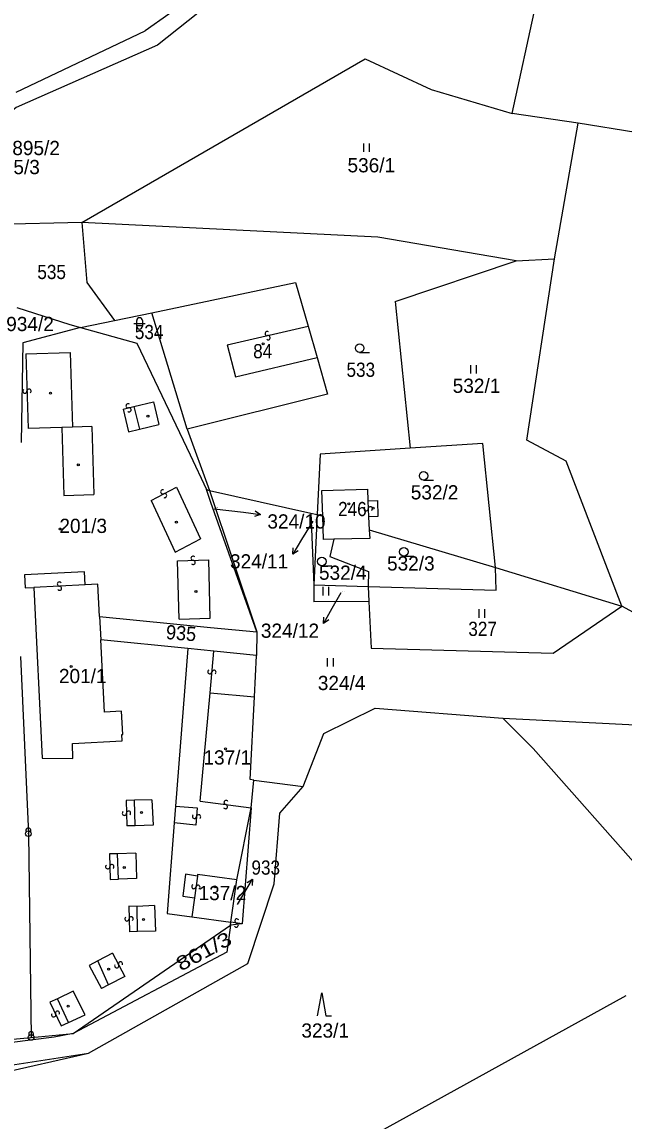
# Model space of a CAD drawing. Extents: x -680102 to -677253, y -1007548 to -1006096.
# Drawn here: x -679408.3 to -679302.6, y -1007390.7 to -1007197.5 of the extents above; entities that cross this region are included whole.
import ezdxf
from ezdxf.enums import TextEntityAlignment as Align

# ---------------------------------------------------------------- set-up
doc = ezdxf.new("R2010")
doc.units = 0
for name, color, linetype, lineweight in [('1', 7, 'Continuous', 25), ('16', 7, 'Continuous', 25), ('24', 7, 'Continuous', 25), ('25', 7, 'Continuous', 25), ('4', 7, 'Continuous', 25)]:
    doc.layers.add(name, color=color, linetype=linetype, lineweight=lineweight)
doc.layers.add('18', color=7, linetype='Continuous')
doc.layers.add('19', color=7, linetype='Continuous')

msp = doc.modelspace()

# ---------------------------------------------------------------- linework, layer by layer
at = {"layer": '1'}
for p, q in [((-679373.36, -1007189.63), (-679386.69, -1007199.1)), ((-679409.36, -1007209.85), (-679386.69, -1007199.1)), ((-679397.84, -1007232.76), (-679414.73, -1007233.19)), ((-679345.8, -1007235.33), (-679397.84, -1007232.76)), ((-679397.84, -1007232.76), (-679396.93, -1007243.35)), ((-679321.52, -1007239.5), (-679345.8, -1007235.33)), ((-679342.81, -1007246.67), (-679321.52, -1007239.5)), ((-679321.52, -1007239.5), (-679314.77, -1007239.17)), ((-679396.93, -1007243.35), (-679392.07, -1007249.98)), ((-679342.81, -1007246.67), (-679340.14, -1007272.45)), ((-679398.04, -1007251.22), (-679392.07, -1007249.98)), ((-679392.07, -1007249.98), (-679385.54, -1007248.63)), ((-679354.68, -1007262.95), (-679379.3, -1007269.09)), ((-679379.3, -1007269.09), (-679375.41, -1007279.89)), ((-679356.49, -1007284.11), (-679355.52, -1007284.4)), ((-679353.57, -1007288.47), (-679354.24, -1007291.5)), ((-679347.33, -1007286.83), (-679325.17, -1007293.43)), ((-679354.24, -1007291.5), (-679347.45, -1007294.11)), ((-679347.45, -1007294.11), (-679347.52, -1007296.75)), ((-679325.17, -1007293.43), (-679302.96, -1007300.22)), ((-679347.4, -1007299.4), (-679357.05, -1007299.47)), ((-679315.02, -1007308.51), (-679302.96, -1007300.22)), ((-679274.09, -1007316.01), (-679302.96, -1007300.22)), ((-679394.72, -1007302.06), (-679394.51, -1007306.14)), ((-679379.19, -1007307.69), (-679394.51, -1007306.14)), ((-679347.02, -1007307.6), (-679315.02, -1007308.51)), ((-679408.6, -1007309.08), (-679407.23, -1007340.23)), ((-679346.28, -1007318.15), (-679323.86, -1007319.92)), ((-679318.55, -1007325.27), (-679323.86, -1007319.92)), ((-679323.86, -1007319.92), (-679292.21, -1007321.54)), ((-679291.26, -1007356.13), (-679318.55, -1007325.27)), ((-679367.62, -1007330.81), (-679368.23, -1007330.71)), ((-679407.23, -1007340.23), (-679406.74, -1007376.04)), ((-679368.68, -1007363.03), (-679364.05, -1007349.02)), ((-679382.86, -1007354.24), (-679378.51, -1007354.84)), ((-679378.51, -1007354.84), (-679371.64, -1007355.79)), ((-679396.69, -1007378.79), (-679368.68, -1007363.03)), ((-679429.51, -1007386.31), (-679396.69, -1007378.79)), ((-679428.99, -1007383.8), (-679396.69, -1007378.79))]:
    msp.add_line(p, q, dxfattribs=at)
for points in [[(-679302.96, -1007300.22), (-679312.75, -1007274.71), (-679319.66, -1007271.06), (-679314.77, -1007239.17), (-679310.61, -1007215.32), (-679322.2, -1007213.64), (-679313.91, -1007175.32), (-679331.07, -1007172.92), (-679359.5, -1007170.05), (-679369.48, -1007182.54), (-679372.06, -1007191.61), (-679384.55, -1007201.63), (-679409.35, -1007212.56), (-679417.25, -1007219.13), (-679416.79, -1007226.78)], [(-679397.84, -1007232.76), (-679348.04, -1007204.02), (-679336.46, -1007209.4), (-679322.2, -1007213.64)], [(-679250.2, -1007225.05), (-679280.21, -1007220.22), (-679310.61, -1007215.32)], [(-679379.3, -1007269.09), (-679385.54, -1007248.63), (-679360.27, -1007243.33)], [(-679360.27, -1007243.33), (-679358.08, -1007251.02), (-679356.51, -1007256.53), (-679354.68, -1007262.95)], [(-679409.23, -1007247.72), (-679399.97, -1007250.68), (-679398.04, -1007251.22), (-679408.21, -1007253.91), (-679408.49, -1007271.44)], [(-679398.04, -1007251.22), (-679388.19, -1007253.97), (-679378.8, -1007273.64), (-679375.94, -1007279.74), (-679375.41, -1007279.89), (-679367.06, -1007304.75), (-679373.24, -1007287.45), (-679375.14, -1007282), (-679375.94, -1007279.74)], [(-679327.35, -1007271.62), (-679340.14, -1007272.45), (-679355.98, -1007273.48)], [(-679325.06, -1007297.39), (-679325.17, -1007293.43), (-679327.35, -1007271.62)], [(-679355.98, -1007273.48), (-679356.49, -1007284.11), (-679357.08, -1007296.48)], [(-679375.41, -1007279.89), (-679357.62, -1007283.86), (-679356.49, -1007284.11)], [(-679355.67, -1007279.91), (-679347.63, -1007279.64), (-679347.56, -1007281.7), (-679345.9, -1007281.64), (-679345.81, -1007284.46), (-679347.47, -1007284.51)], [(-679355.38, -1007288.5), (-679355.52, -1007284.4), (-679355.67, -1007279.91)], [(-679357.62, -1007283.86), (-679357.08, -1007296.48), (-679357.05, -1007299.47)], [(-679347.47, -1007284.51), (-679347.33, -1007286.83), (-679347.24, -1007288.36)], [(-679347.24, -1007288.36), (-679353.57, -1007288.47), (-679355.38, -1007288.5)], [(-679394.72, -1007302.06), (-679395.02, -1007296.36), (-679397.23, -1007296.47), (-679397.35, -1007294.18), (-679407.91, -1007294.72), (-679407.79, -1007297.01), (-679406.29, -1007296.94), (-679404.83, -1007326.95)], [(-679357.08, -1007296.48), (-679347.52, -1007296.75), (-679325.06, -1007297.39)], [(-679347.52, -1007296.75), (-679347.4, -1007299.4), (-679347.02, -1007307.6)], [(-679394.72, -1007302.06), (-679375.22, -1007303.96), (-679367.06, -1007304.75), (-679367.15, -1007308.91)], [(-679404.83, -1007326.95), (-679399.39, -1007326.99), (-679399.45, -1007324.35), (-679390.74, -1007323.88), (-679390.8, -1007322.79), (-679390.65, -1007322.78), (-679390.88, -1007318.68), (-679393.84, -1007318.84), (-679394.51, -1007306.14)], [(-679367.15, -1007308.91), (-679374.66, -1007308.15), (-679379.19, -1007307.69), (-679381.37, -1007335.37), (-679381.6, -1007338.34), (-679382.86, -1007354.24)], [(-679368.23, -1007330.71), (-679367.51, -1007316.16), (-679367.15, -1007308.91)], [(-679358.97, -1007331.94), (-679355.33, -1007322.62), (-679346.28, -1007318.15)], [(-679368.08, -1007335.69), (-679367.62, -1007330.81), (-679358.97, -1007331.94)], [(-679364.05, -1007349.02), (-679363.03, -1007336.62), (-679358.97, -1007331.94)], [(-679370.63, -1007348.32), (-679368.08, -1007335.69), (-679369.66, -1007356.06)], [(-679371.64, -1007355.79), (-679370.63, -1007348.32), (-679377.5, -1007347.38), (-679377.54, -1007347.67), (-679379.64, -1007347.34), (-679380.07, -1007351.23), (-679378.06, -1007351.5), (-679378.51, -1007354.84)], [(-679369.66, -1007356.06), (-679371.7, -1007356.28), (-679371.64, -1007355.79)], [(-679392.55, -1007422.66), (-679354.27, -1007397.43), (-679302.19, -1007368.68)], [(-679399.37, -1007375.35), (-679402.68, -1007375.99), (-679414.28, -1007377.44), (-679422.91, -1007378.34), (-679418.33, -1007374.49), (-679415.13, -1007376.82)], [(-679415.13, -1007376.82), (-679406.74, -1007376.04), (-679399.37, -1007375.35)]]:
    msp.add_lwpolyline(points, dxfattribs=at)
msp.add_lwpolyline([(-679371.7, -1007356.28), (-679372.34, -1007361.03), (-679399.37, -1007375.35)], close=True, dxfattribs=at)
at = {"layer": '16'}
for p, q in [((-679374.56, -1007283.1), (-679369.41, -1007283.72)), ((-679369.41, -1007283.72), (-679366.433, -1007284.085)), ((-679357.25, -1007285.26), (-679359.23, -1007288.53)), ((-679359.23, -1007288.53), (-679360.788, -1007291.093)), ((-679352.35, -1007297.86), (-679353.9, -1007300.66)), ((-679353.9, -1007300.66), (-679355.354, -1007303.283)), ((-679369.37, -1007350.78), (-679367.848, -1007348.196)), ((-679370.5, -1007352.7), (-679369.37, -1007350.78))]:
    msp.add_line(p, q, dxfattribs=at)
for points in [[(-679367.364, -1007283.468), (-679366.433, -1007284.085), (-679367.486, -1007284.46)], [(-679359.841, -1007290.498), (-679360.788, -1007291.093), (-679360.696, -1007289.979)], [(-679354.432, -1007302.651), (-679355.354, -1007303.283), (-679355.306, -1007302.166)], [(-679368.786, -1007348.803), (-679367.848, -1007348.196), (-679367.925, -1007349.311)]]:
    msp.add_lwpolyline(points, dxfattribs=at)
at = {"layer": '24'}
for centre, radius in [((-679407.23, -1007340.23), 0.5), ((-679407.23, -1007340.23), 0.022), ((-679406.74, -1007376.04), 0.5), ((-679406.74, -1007376.04), 0.022)]:
    msp.add_circle(centre, radius, dxfattribs=at)
for centre in [(-679407.231, -1007339.667), (-679406.741, -1007375.477)]:
    msp.add_arc(centre, 0.437, 328.35109, 209.97456, dxfattribs=at)
at = {"layer": '25'}
for p, q in [((-679348.297, -1007220.365), (-679348.297, -1007218.865)), ((-679347.263, -1007220.365), (-679347.263, -1007218.865)), ((-679388.2, -1007251.01), (-679388.2, -1007250.01)), ((-679387.2, -1007250.01), (-679387.2, -1007251.01)), ((-679388.7, -1007250.51), (-679386.7, -1007250.51)), ((-679349.02, -1007255.63), (-679347.27, -1007255.63)), ((-679329.507, -1007259.345), (-679329.507, -1007257.845)), ((-679328.473, -1007259.345), (-679328.473, -1007257.845)), ((-679337.78, -1007278.06), (-679336.03, -1007278.06)), ((-679341.25, -1007291.43), (-679339.5, -1007291.43)), ((-679355.67, -1007293.11), (-679353.92, -1007293.11)), ((-679355.457, -1007298.355), (-679355.457, -1007296.855)), ((-679354.423, -1007298.355), (-679354.423, -1007296.855)), ((-679328.037, -1007302.275), (-679328.037, -1007300.775)), ((-679327.003, -1007302.275), (-679327.003, -1007300.775)), ((-679354.677, -1007310.855), (-679354.677, -1007309.355)), ((-679353.643, -1007310.855), (-679353.643, -1007309.355))]:
    msp.add_line(p, q, dxfattribs=at)
msp.add_lwpolyline([(-679356.44, -1007372.22), (-679355.69, -1007368.22), (-679354.94, -1007372.22), (-679353.94, -1007372.22)], dxfattribs=at)
for centre, radius in [((-679365.96, -1007254.1), 0.175), ((-679349.02, -1007254.88), 0.75), ((-679403.33, -1007262.77), 0.175), ((-679386.21, -1007266.83), 0.175), ((-679398.45, -1007275.37), 0.175), ((-679337.78, -1007277.31), 0.75), ((-679350.94, -1007282.24), 0.175), ((-679346.67, -1007283.02), 0.175), ((-679401.64, -1007286.66), 0.175), ((-679381.23, -1007285.44), 0.175), ((-679341.25, -1007290.68), 0.75), ((-679355.67, -1007292.36), 0.75), ((-679377.78, -1007297.64), 0.175), ((-679399.69, -1007310.84), 0.175), ((-679372.6, -1007325.32), 0.175), ((-679387.33, -1007336.51), 0.175), ((-679390.37, -1007346.16), 0.175), ((-679374.45, -1007349.59), 0.175), ((-679387.02, -1007355.31), 0.175), ((-679393.12, -1007364.06), 0.175), ((-679400.23, -1007370.56), 0.175)]:
    msp.add_circle(centre, radius, dxfattribs=at)
for centre, radius, start, end in [((-679387.7, -1007250.01), 0.5, 0.101, 180.00143), ((-679387.7, -1007251.01), 0.5, 180.10243, 0.00286), ((-679365.27, -1007252.311), 0.367, 50.63133, 282.56485), ((-679365.112, -1007253.03), 0.368, 230.39527, 102.22879), ((-679407.838, -1007262.437), 0.368, 129.17022, 0.83864), ((-679407.103, -1007262.422), 0.368, 308.60193, 181.2502), ((-679389.714, -1007265.002), 0.367, 51.25638, 283.20709), ((-679389.548, -1007265.719), 0.368, 230.95326, 103.14222), ((-679383.618, -1007280.133), 0.368, 64.72626, 297.19472), ((-679383.283, -1007280.789), 0.369, 244.96627, 117.19988), ((-679347.889, -1007283.117), 0.369, 129.26853, 0.9723), ((-679347.153, -1007283.101), 0.367, 308.91356, 181.40624), ((-679378.289, -1007291.803), 0.367, 39.02463, 271.40695), ((-679378.273, -1007292.539), 0.369, 219.26925, 91.22705), ((-679401.774, -1007296.342), 0.368, 40.26409, 272.29388), ((-679401.744, -1007297.077), 0.367, 220.09095, 92.49706), ((-679375.346, -1007311.764), 0.367, 122.13866, 354.38524), ((-679374.613, -1007311.837), 0.368, 302.13965, 174.24728), ((-679372.5, -1007334.746), 0.367, 30.04932, 262.18073), ((-679390.358, -1007336.638), 0.368, 129.38882, 1.24824), ((-679389.623, -1007336.62), 0.368, 309.21441, 181.56225), ((-679378.047, -1007337.19), 0.368, 123.47517, 355.32964), ((-679377.314, -1007337.248), 0.367, 302.80484, 175.62663), ((-679372.602, -1007335.475), 0.368, 209.97812, 81.73883), ((-679393.288, -1007346.038), 0.368, 129.38882, 1.24824), ((-679392.553, -1007346.02), 0.368, 309.21441, 181.56225), ((-679378.164, -1007349.535), 0.368, 119.63001, 351.41047), ((-679377.437, -1007349.643), 0.367, 299.2949, 171.69456), ((-679389.909, -1007355.214), 0.369, 128.61228, 0.25138), ((-679389.172, -1007355.204), 0.368, 308.62242, 180.93553), ((-679370.703, -1007356.293), 0.367, 209.49992, 81.69384), ((-679370.595, -1007355.566), 0.368, 29.62929, 261.5684), ((-679391.699, -1007363.457), 0.369, 154.96556, 26.92022), ((-679391.043, -1007363.122), 0.368, 334.64089, 207.194), ((-679402.116, -1007371.777), 0.368, 332.29535, 204.61338), ((-679402.785, -1007372.083), 0.368, 152.39453, 24.27059)]:
    msp.add_arc(centre, radius, start, end, dxfattribs=at)
at = {"layer": '4'}
for p, q in [((-679372.31, -1007254.31), (-679358.08, -1007251.02)), ((-679407.68, -1007255.89), (-679407.27, -1007268.97)), ((-679396.1, -1007268.63), (-679399.47, -1007268.73)), ((-679396.1, -1007268.63), (-679395.73, -1007280.6)), ((-679347.56, -1007281.7), (-679347.47, -1007284.51)), ((-679381.03, -1007292.26), (-679375.53, -1007292.07)), ((-679380.76, -1007302.52), (-679381.03, -1007292.26)), ((-679375.26, -1007302.33), (-679375.53, -1007292.07)), ((-679397.23, -1007296.47), (-679406.29, -1007296.94)), ((-679380.76, -1007302.52), (-679375.26, -1007302.33)), ((-679375.31, -1007315.45), (-679367.51, -1007316.16)), ((-679390.07, -1007334.38), (-679389.91, -1007338.87)), ((-679388.46, -1007338.82), (-679388.61, -1007334.35)), ((-679377.02, -1007334.52), (-679368.08, -1007335.69)), ((-679381.37, -1007335.37), (-679377.57, -1007335.69)), ((-679377.57, -1007335.69), (-679377.78, -1007338.74)), ((-679377.78, -1007338.74), (-679381.6, -1007338.34)), ((-679393, -1007343.77), (-679392.84, -1007348.29)), ((-679388.37, -1007343.65), (-679391.57, -1007343.79)), ((-679377.54, -1007347.67), (-679378.06, -1007351.5)), ((-679389.59, -1007352.94), (-679389.48, -1007357.48)), ((-679388.14, -1007353), (-679389.59, -1007352.94)), ((-679385.06, -1007352.86), (-679388.14, -1007353)), ((-679388.03, -1007357.44), (-679388.14, -1007353)), ((-679369.66, -1007356.06), (-679371.64, -1007355.79)), ((-679392.44, -1007361.25), (-679390.3, -1007365.33)), ((-679396.53, -1007363.37), (-679394.39, -1007367.45)), ((-679393.12, -1007366.79), (-679395.02, -1007362.59)), ((-679399.38, -1007367.9), (-679402.11, -1007369.24)), ((-679402.11, -1007369.24), (-679403.43, -1007369.84)), ((-679403.43, -1007369.84), (-679401.48, -1007374.02)), ((-679400.17, -1007373.41), (-679402.11, -1007369.24))]:
    msp.add_line(p, q, dxfattribs=at)
for points in [[(-679407.68, -1007255.89), (-679399.88, -1007255.65), (-679399.47, -1007268.73)], [(-679372.31, -1007254.31), (-679370.83, -1007259.88), (-679356.51, -1007256.53)], [(-679390.58, -1007265.59), (-679388.68, -1007265.13), (-679385.24, -1007264.3), (-679384.28, -1007268.26)], [(-679388.68, -1007265.13), (-679387.72, -1007269.09), (-679384.28, -1007268.26)], [(-679390.58, -1007265.59), (-679389.62, -1007269.55), (-679387.72, -1007269.09)], [(-679399.47, -1007268.73), (-679401.37, -1007268.79), (-679407.27, -1007268.97)], [(-679401.37, -1007268.79), (-679401, -1007280.76), (-679395.73, -1007280.6)], [(-679385.68, -1007281.63), (-679381.22, -1007279.29), (-679376.99, -1007288.38)], [(-679385.68, -1007281.63), (-679381.45, -1007290.73), (-679376.99, -1007288.38)], [(-679377.02, -1007334.52), (-679375.31, -1007315.45), (-679374.66, -1007308.15)], [(-679385.55, -1007334.29), (-679388.61, -1007334.35), (-679390.07, -1007334.38)], [(-679385.55, -1007334.29), (-679385.31, -1007338.71), (-679388.46, -1007338.82), (-679389.91, -1007338.87)], [(-679392.84, -1007348.29), (-679391.41, -1007348.24), (-679391.57, -1007343.79), (-679393, -1007343.77)], [(-679388.37, -1007343.65), (-679388.24, -1007348.13), (-679391.41, -1007348.24)], [(-679385.06, -1007352.86), (-679384.88, -1007357.37), (-679388.03, -1007357.44), (-679389.48, -1007357.48)], [(-679392.44, -1007361.25), (-679395.02, -1007362.59), (-679396.53, -1007363.37)], [(-679390.3, -1007365.33), (-679393.12, -1007366.79), (-679394.39, -1007367.45)], [(-679401.48, -1007374.02), (-679400.17, -1007373.41), (-679397.27, -1007372.05), (-679399.38, -1007367.9)]]:
    msp.add_lwpolyline(points, dxfattribs=at)

# ---------------------------------------------------------------- texts
at = {"layer": '16'}
for s, p in [('895/2', (-679410.05, -1007220.93)), ('895/3', (-679413.58, -1007224.28)), ('324/10', (-679365.23, -1007286.58))]:
    msp.add_text(s, height=2.5, dxfattribs=at).set_placement(p)
for s, p in [('324/11', (-679361.58, -1007293.6)), ('324/12', (-679356.15, -1007305.79))]:
    msp.add_text(s, height=2.5, dxfattribs=at).set_placement(p, align=Align.RIGHT)
at = {"layer": '16', "width": 0.9}
msp.add_text('933', height=2.5, dxfattribs=at).set_placement((-679368.03, -1007347.43))
at = {"layer": '18'}
for s, p in [('536/1', (-679346.97, -1007223.96)), ('532/1', (-679328.49, -1007262.73)), ('323/1', (-679355.079, -1007376.08))]:
    msp.add_text(s, height=2.5, dxfattribs=at).set_placement(p, align=Align.CENTER)
at = {"layer": '18', "width": 0.9}
for s, height, p in [('535', 2.5, (-679405.65, -1007242.72)), ('534', 2.5, (-679388.52, -1007253.27)), ('933', 0.1, (-679370.3, -1007352.5))]:
    msp.add_text(s, height=height, dxfattribs=at).set_placement(p)
at = {"layer": '18'}
for s, height, p in [('934/2', 2.5, (-679411.12, -1007251.87)), ('532/2', 2.5, (-679340.04, -1007281.46)), ('324/10', 0.1, (-679374.36, -1007282.9)), ('324/11', 0.1, (-679357.05, -1007285.06)), ('532/3', 2.5, (-679344.21, -1007293.96)), ('532/4', 2.5, (-679356.17, -1007295.59)), ('324/12', 0.1, (-679352.15, -1007297.66)), ('324/4', 2.5, (-679356.37, -1007314.98))]:
    msp.add_text(s, height=height, dxfattribs=at).set_placement(p)
at = {"layer": '18', "width": 0.9}
for s, p in [('533', (-679348.819, -1007259.91)), ('327', (-679327.419, -1007305.46))]:
    msp.add_text(s, height=2.5, dxfattribs=at).set_placement(p, align=Align.CENTER)
at = {"layer": '18'}
for s, rotation, width, p in [('935', 355.603, 0.95, (-679383.126, -1007306.006)), ('861/3', 28.2, 1.25, (-679380.429, -1007364.47))]:
    msp.add_text(s, height=2.5, rotation=rotation, dxfattribs=dict(at, width=width)).set_placement(p)
at = {"layer": '19', "width": 0.9}
msp.add_text('84', height=2.5, dxfattribs=at).set_placement((-679366.059, -1007256.65), align=Align.CENTER)
msp.add_text('246', height=2.5, dxfattribs=at).set_placement((-679352.81, -1007284.4))
at = {"layer": '19'}
for s, p in [('201/3', (-679397.59, -1007287.36)), ('137/1', (-679372.29, -1007328.07))]:
    msp.add_text(s, height=2.5, dxfattribs=at).set_placement(p, align=Align.CENTER)
for s, p in [('201/1', (-679401.86, -1007313.76)), ('137/2', (-679377.33, -1007351.91))]:
    msp.add_text(s, height=2.5, dxfattribs=at).set_placement(p)

doc.saveas('drawing.dxf')
